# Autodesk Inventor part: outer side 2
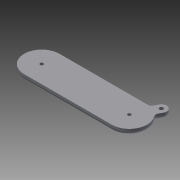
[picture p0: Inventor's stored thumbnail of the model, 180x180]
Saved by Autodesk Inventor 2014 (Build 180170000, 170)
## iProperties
Created: 2015-01
Part Number: outer side 2
Material: Generic
Document SubType Name: Modeling
Designer: Drano
Density: 1 g/cm^3
Appearance: Default
Author: Drano
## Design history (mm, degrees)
sketch "Sketch1"
  geometry: L1 (-35.603, -15.338)-(41.397, -15.338); L2 (-35.603, 15.662)-(41.397, 15.662); L3 (46.826, 20.866)-(44.988, 17.273); L4 (55.009, 16.679)-(53.172, 13.087); C1 r 1.5 at (-35.603, 0.162); C2 r 1.5 at (41.397, 0.162); C3 r 1.75 at (50.917, 18.773); A1 r 15.5 centre (41.397, 0.162) between (41.397, -15.338) and (53.5, 9.846); A2 r 3 centre (55.842, 11.721) between (53.172, 13.087) and (53.5, 9.846); A3 r 15.5 centre (41.397, 0.162) between (42.168, 15.643) and (41.397, 15.662); A4 r 3 centre (42.317, 18.64) between (42.168, 15.643) and (44.988, 17.273); A5 r 15.5 centre (-35.603, 0.162) between (-35.603, 15.662) and (-35.603, -15.338); A6 r 4.596 centre (50.917, 18.773) between (55.009, 16.679) and (46.826, 20.866); 1 further point
  constraints: 12 point on circle, 9 centre point, 8 end point
extrude "Extrusion1" new body sketch "Sketch1" distance "d0" = 5; taper "d1" = 0 deg
fillet "Fillet1" dims "d2" = 3
feature "Lip1" dims "d3" = 2.5, "d4" = 1.5, "d5" = 0, "d6" = 0, "d7" = 0, "d8" = 0
feature "Lip2" dims "d9" = 2.5, "d10" = 1.5, "d11" = 0, "d12" = 0, "d13" = 0, "d14" = 0
body "Solid1"
